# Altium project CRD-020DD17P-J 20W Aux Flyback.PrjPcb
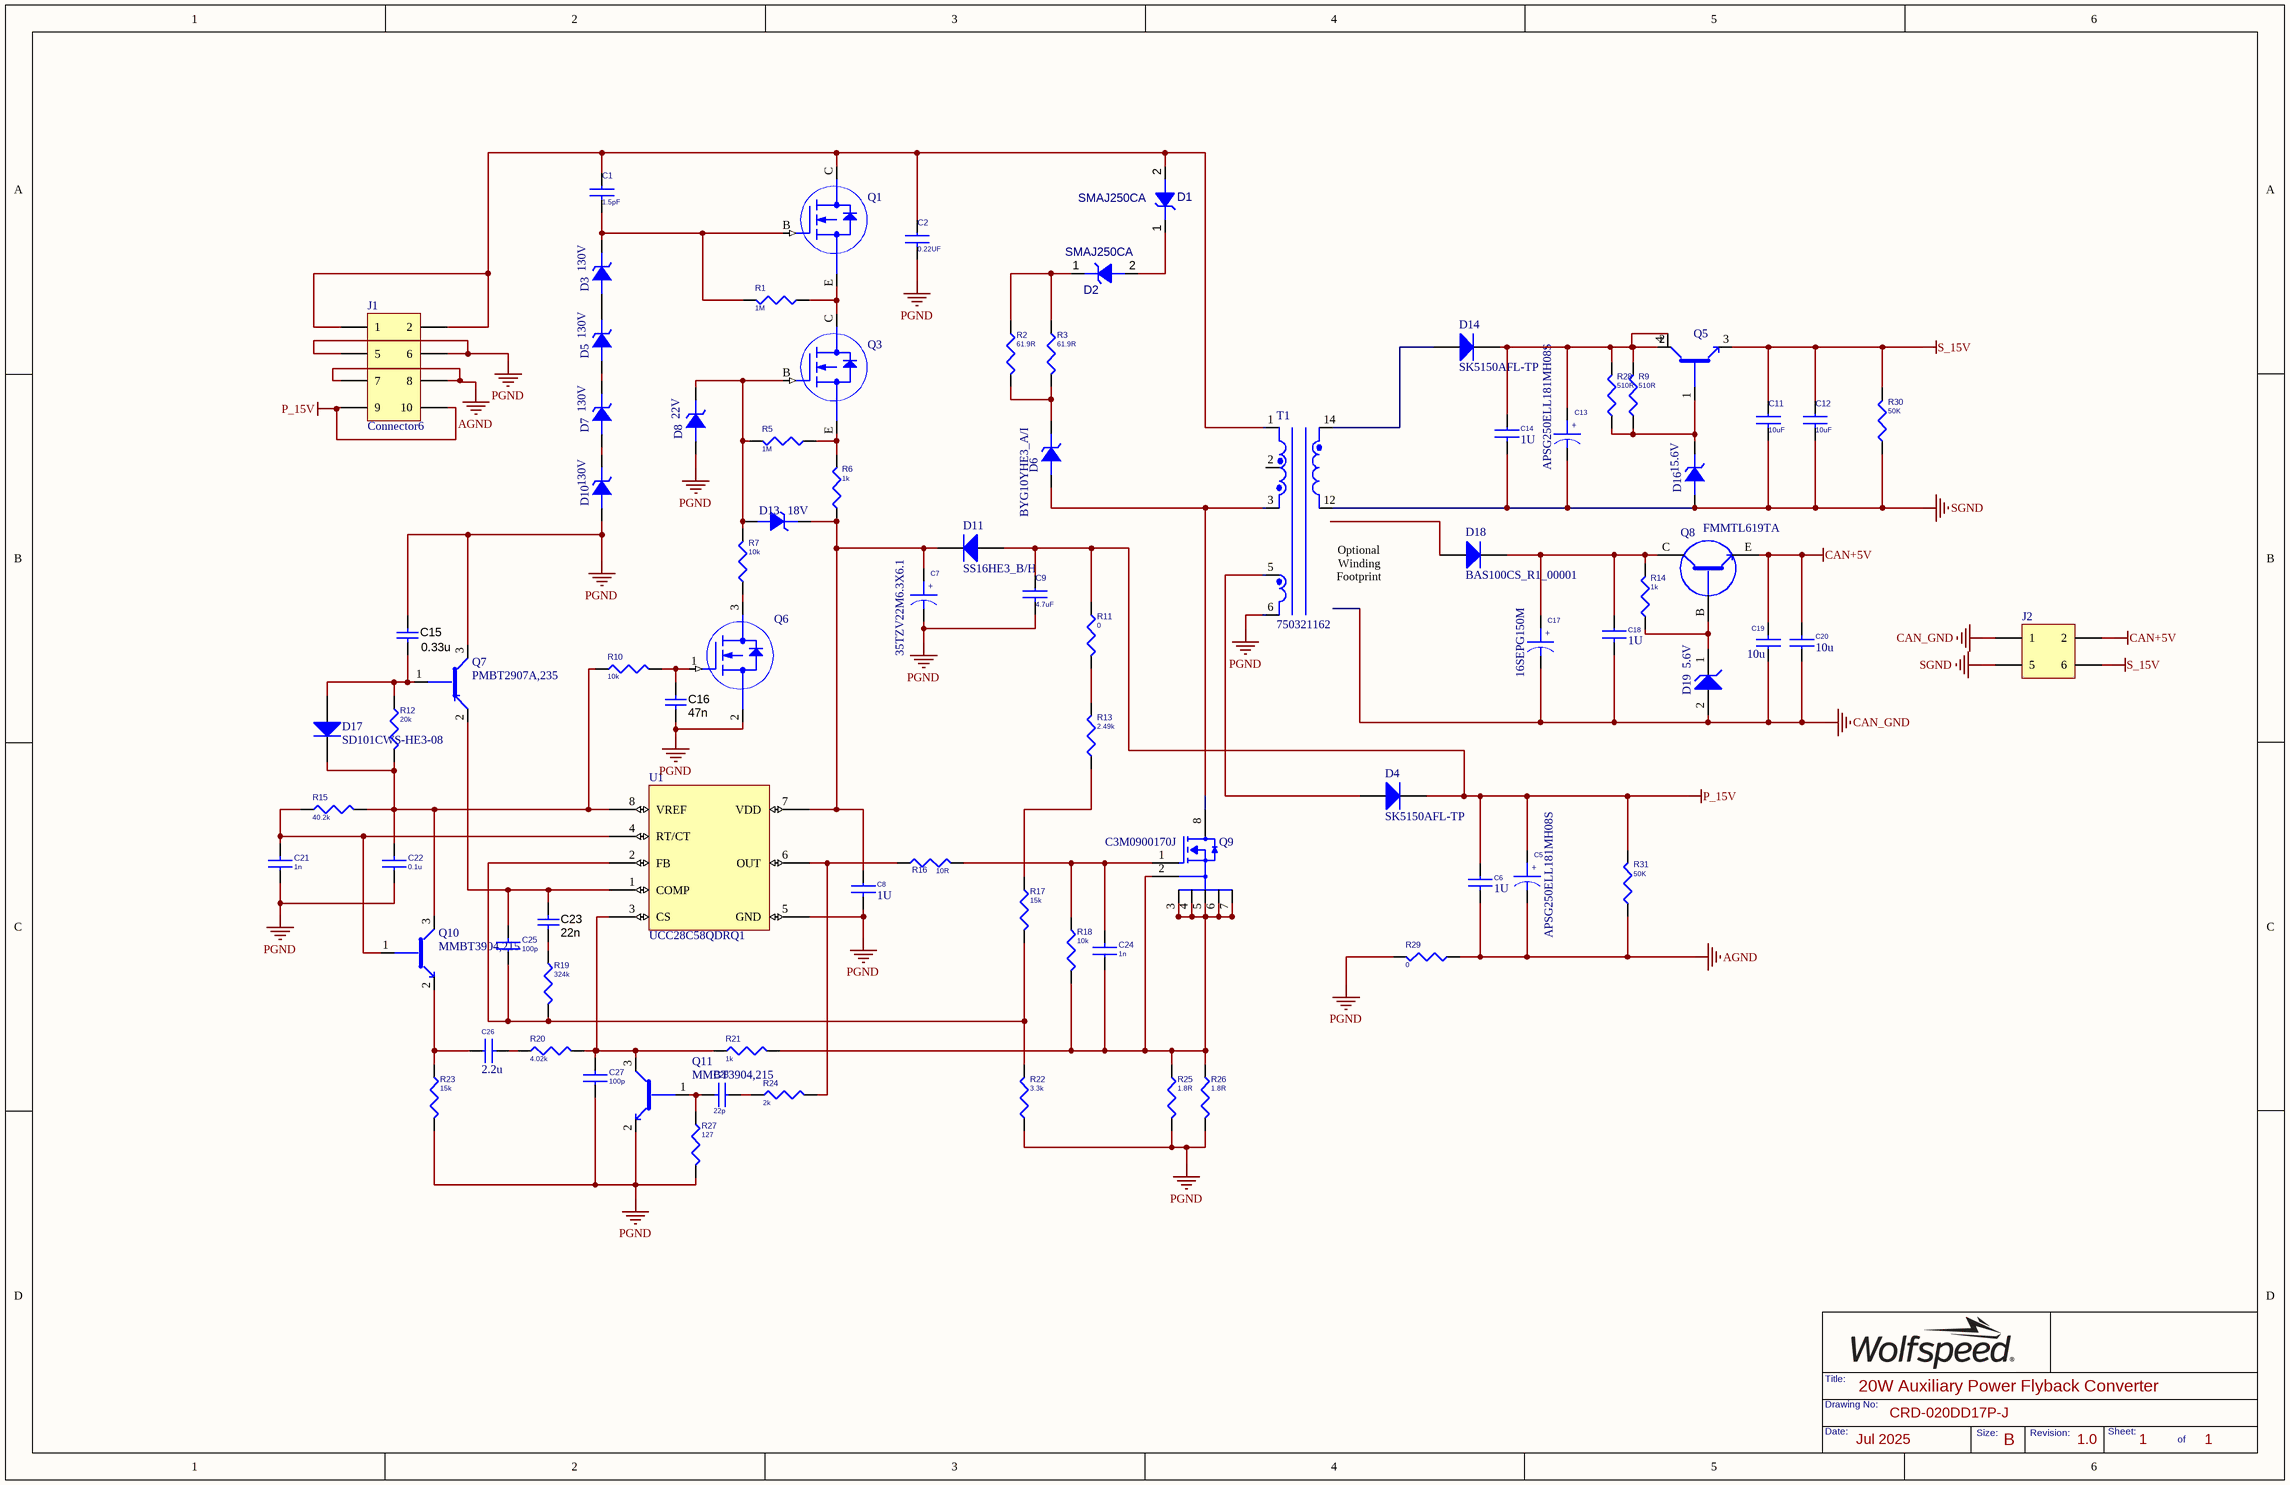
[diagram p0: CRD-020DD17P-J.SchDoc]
Title: 20W Auxiliary Power Flyback Converter; Revision: 1.0; DocumentNumber: CRD-020DD17P-J; Date: Jul 2025
1 sheet, 83 parts. Net scope: global (net labels, ports and power ports of the same name join across sheets).
Board file: CRD-020DD17P-J.PcbDoc

## Sheet CRD-020DD17P-J.SchDoc: 20W Auxiliary Power Flyback Converter
size 431 x 279 mm; SheetNumber: 1; SheetTotal: 1

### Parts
C1  1.5pF  [C1206]
C2  0.22UF  [C2220]
C5  APSG250ELL181MH08S  [C7C9C13-RNU1E221MDNASQ]
C6  1U  [C0603]
C7  35TZV22M6.3X6.1  [CAP6_6X6_6]
C8  1U  [C0603]
C9  4.7uF  [C1206]
C11  10uF  [C1206]
C12  10uF  [C1206]
C13  APSG250ELL181MH08S  [C7C9C13-RNU1E221MDNASQ]
C14  1U  [C0603]
C15  0.33u  [0603]
C16  47n  [0603]
C17  16SEPG150M  [C17_16SEPG150M]
C18  1U  [C0603]
C19  10u  [C0805]
C20  10u  [C0805]
C21  1n  [C0603]
C22  0.1u  [C0603]
C23  22n  [0603]
C24  1n  [C0603]
C25  100p  [C0603]
C26  2.2u  [0603]
C27  100p  [C0603]
C28  22p  [C0603]
D1  SMAJ250CA  [DO-214AC_SMA_B]
D2  SMAJ250CA  [DO-214AC_SMA_B]
D3  130V  [SOD-323F]
D4  SK5150AFL-TP  [DO221AC]
D5  130V  [SOD-323F]
D6  BYG10YHE3_A/I  [DO214AC]
D7  130V  [SOD-323F]
D8  22V  [SOD323]
D10  130V  [SOD-323F]
D11  SS16HE3_B/H  [SMA]
D13  18V  [SOD323]
D14  SK5150AFL-TP  [DO221AC]
D16  15.6V  [DO220AA]
D17  SD101CWS-HE3-08  [SOD323]
D18  BAS100CS_R1_00001  [SOD323]
D19  5.6V  [ONSC-SOD-123-2-425-04_V]
J1  Connector6  [HPR2X4H-254MM-80]
J2  Connector6  [HPR2X3H-254MM-90]  (value not drawn)
Q1  TO247-3  [SOT23-3]  (value not drawn)
Q3  TO247-3  [SOT23-3]  (value not drawn)
Q5  PBSS306NZ,135  [SOT223]  (value not drawn)
Q6  (no value)  [TO236AB]
Q7  PMBT2907A,235  [TO236AB]
Q8  FMMTL619TA  [SOT23-3]
Q9  C3M0900170J  [TO-263-7XL_CRW]
Q10  MMBT3904,215  [TO-236AB]
Q11  MMBT3904,215  [TO-236AB]
R1  1M  [R0603]
R2  61.9R  [R2010]
R3  61.9R  [R2010]
R5  1M  [R0603]
R6  1k  [R0603]
R7  10k  [R0603]
R9  510R  [R1206]
R10  10k  [R0603]
R11  0  [R0603]
R12  20k  [R0603]
R13  2.49k  [R0603]
R14  1k  [R0805]
R15  40.2k  [R0603]
R16  10R  [1206]
R17  15k  [R0603]
R18  10k  [R0603]
R19  324k  [R0603]
R20  4.02k  [R0603]
R21  1k  [R0603]
R22  3.3k  [R0603]
R23  15k  [R0603]
R24  2k  [R0603]
R25  1.8R  [R1206]
R26  1.8R  [R1206]
R27  127  [R0805]
R28  510R  [R1206]
R29  0  [R1206]
R30  50K  [R1206]
R31  50K  [R1206]
T1  750321162  [750345357-Footprint-1]
U1  UCC28C58QDRQ1  [SOIC-8]

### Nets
AGND: C5.2 C6.2 J1.7 J1.8 R29.1 R31.1
CAN+5V: C19.2 C20.2 J2.2 Q8.E
CAN_GND: C17.2 C18.2 C19.1 C20.1 D19.2(A) J2.1
P_15V: C5.1 C6.1 C9.1 D4.2(K) D11.1(A) J1.9 J1.10 R11.1 R31.2
PGND: C2.2 C7.2 C8.2 C9.2 C15.2 C16.1 C21.1 C22.1 C27.1 D8.1(ANODE) D10.1(ANODE) J1.5 J1.6 Q6.2(SOURCE1) Q7.3 Q11.2 R22.1 R23.2 R25.2 R26.2 R27.2 R29.2 T1.6(Pri2-) U1.5(GND)
S_15V: C11.1 C12.1 J2.6 Q5.3 R30.2
SGND: C11.2 C12.2 C13.2 C14.2 D16.1(ANODE) J2.5 R30.1 T1.12(Sec1-)
NetC1_1: C1.1 C2.1 D1.2(A) J1.1 J1.2 Q1.C T1.1(Pri1+)
NetC1_2: C1.2 D3.2(CATHODE) Q1.B R1.2
NetC7_1: C7.1 C8.1 D11.2(K) D13.2(CATHODE) R6.1 U1.7(VDD)
NetC13_1: C13.1 C14.1 D14.2(K) Q5.2 Q5.4 R9.2 R28.2
NetC15_1: C15.1 D17.1(A) Q7.1 R12.1
NetC16_2: C16.2 Q6.1(GATE) R10.2
NetC17_1: C17.1 C18.1 D18.2(K) Q8.C R14.2
NetC21_2: C21.2 Q10.1 R15.1 U1.4(RT/CT)
NetC22_2: C22.2 D17.2(K) Q10.3 R10.1 R12.2 R15.2 U1.8(VREF)
NetC23_1: C23.1 R19.1
NetC23_2: C23.2 C25.2 Q7.2 U1.1(COMP)
NetC24_1: C24.1 Q9.2(Driver_Source) Q9.3(Power_Source) Q9.4(Power_Source) Q9.5(Power_Source) Q9.6(Power_Source) Q9.7(Power_Source) R18.2 R21.2 R25.1 R26.1
NetC24_2: C24.2 Q9.1(Gate) R16.2 R18.1
NetC25_1: C25.1 R17.2 R19.2 R22.2 U1.2(FB)
NetC26_1: C26.1 Q10.2 R23.1
NetC26_2: C26.2 R20.1
NetC27_2: C27.2 Q11.3 R20.2 R21.1 U1.3(CS)
NetC28_1: C28.1 R24.1
NetC28_2: C28.2 Q11.1 R27.1
NetD1_1: D1.1(A) D2.2(A)
NetD2_1: D2.1(A) R2.1 R3.1
NetD3_1: D3.1(ANODE) D5.2(CATHODE)
NetD4_1: D4.1(A) T1.5(Pri2+)
NetD5_1: D5.1(ANODE) D7.2(CATHODE)
NetD6_1: D6.1(ANODE) Q9.8(Drain) T1.3(Pri1-)
NetD6_2: D6.2(CATHODE) R2.2 R3.2
NetD7_1: D7.1(ANODE) D10.2(CATHODE)
NetD8_2: D8.2(CATHODE) D13.1(ANODE) Q3.B R5.2 R7.2
NetD14_1: D14.1(A) T1.14(Sec1+)
NetD16_2: D16.2(CATHODE) Q5.1 R9.1 R28.1
NetD19_1: D19.1(K) Q8.B R14.1
NetQ1_E: Q1.E Q3.C R1.1
NetQ3_E: Q3.E R5.1 R6.2
NetQ6_3: Q6.3(DRAIN) R7.1
NetR11_2: R11.2 R13.2
NetR13_1: R13.1 R17.1
NetR16_1: R16.1 R24.2 U1.6(OUT)

Not connected (* = marked no-connect by the designer): D18 1(A); T1 2(Pri1+)

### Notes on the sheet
- (near T1) Optional Winding Footprint

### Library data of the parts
C1 = CAP NP_Dup1: CAP CER 1.5PF 1KV C0G/NP0 1206; Manufacturer: Knowles Syfer; PN: 1206Y1K01P50DAR
C2 = CAP NP_Dup1: CAP CER 0.22UF 1.2KV X7R 2220; Manufacturer: Knowles Syfer; PCB Footprint: C1206; PN: 2220Y1K20224KXTWS3
C5 C13 = CAP POL: CAP ALUM POLY 180UF 20% 25V T/H; Manufacturer: UCC; PCB Footprint: ecap_d18p7_5
C6 C8 C14 C18 = CAP NP: CAP CER 1UF 25V X7R 0603; Manufacturer: Murata; PN: GRM188R71E105KA12D
C7 = CAP POL: CAP ALUM 22UF 20% 35V SMD; Manufacturer: Rubycon; PCB Footprint: ecap_d18p7_5
C9 = CAP NP_Dup1: CAP CER 4.7UF 50V X7R 1206; Manufacturer: Yageo; PN: CC1206KFX7R9BB475
C11 C12 = CAP NP_Dup1: CAP CER 10UF 25V X7R 1206; Manufacturer: Yageo; PN: CC1206KKX7R8BB106
C15 = CGA3E2X7R1E104K080AA: CAP CER 0.33UF 25V X7R 0603; Manufacturer: Yageo; Polarized: N; CompType: Capacitor; Value: 0.1uF; ValueDisplayed: 33n; U/M: EA; Cap_F: 0.0000001; Tolerance_%: 10; VDC_V: 25; TaMin_C: -55; TaMax_C: 125; SizeArea_mm2: 1.28; SizeAreaWB_mm2: 4.68; SizeX_mm: 1.6; SizeY_mm: 0.8; SizeZ_mm: 1; AEC Category: Q200; AEC Qualified: Y; PN: CC0603KRX7R8BB334
C16 = CGA3E2X7R1E104K080AA: CAP CER 0.047UF 50V X7R 0603; Manufacturer: Yageo; Polarized: N; CompType: Capacitor; Value: 0.1uF; ValueDisplayed: 33n; U/M: EA; Cap_F: 0.0000001; Tolerance_%: 10; VDC_V: 25; Value2: 25V; TaMin_C: -55; TaMax_C: 125; SizeArea_mm2: 1.28; SizeAreaWB_mm2: 4.68; SizeX_mm: 1.6; SizeY_mm: 0.8; SizeZ_mm: 1; AEC Category: Q200; AEC Qualified: Y; PN: AC0603KRX7R9BB473
C17 = CAP POL: CAP ALUM POLY 150UF 20% 16V T/H; Manufacturer: Panasonic; PCB Footprint: ecap_d18p7_5
C19 C20 = CAP NP: CAP CER 10UF 16V X7R 0805; Manufacturer: Yageo; PCB Footprint: 0805; PN: CC0805MKX7R7BB106
C21 C24 = CAP NP_Dup1: CAP CER 1000PF 25V X7R 0603; Manufacturer: Yageo; PN: CC0603MRX7R9BB102
C22 = CAP NP_Dup1: CAP CER 0.1UF 50V X7R 0603; Manufacturer: Yageo; PN: CC0603MRX7R9BB104
C23 = CGA3E2X7R1E104K080AA: CAP CER 0.022UF 50V X7R 0603; Manufacturer: Yageo; Polarized: N; CompType: Capacitor; Value: 0.1uF; ValueDisplayed: 33n; U/M: EA; Cap_F: 0.0000001; Tolerance_%: 10; VDC_V: 25; Value2: 25V; TaMin_C: -55; TaMax_C: 125; SizeArea_mm2: 1.28; SizeAreaWB_mm2: 4.68; SizeX_mm: 1.6; SizeY_mm: 0.8; SizeZ_mm: 1; AEC Category: Q200; AEC Qualified: Y; PN: AC0603KRX7R9BB223
C25 C27 = CAP NP_Dup1: CAP CER 100PF 25V X7R 0603; Manufacturer: Yageo; PN: CC0603MRX7R9BB101
C26 = CAP NP: CAP CER 2.2UF 25V X7R 0603; Manufacturer: Murata; PCB Footprint: C0805; PN: GRM188Z71E225ME43D
C28 = CAP NP_Dup1: CAP CER 22PF 50V C0G/NPO 0603; Manufacturer: Yageo; PN: CC0603KRNPO9BN220
D1 D2 = CMP-004-00090-2: TVS DIODE 250VWM 405VC DO214AC405V Clamp 1A Ipp Tvs Diode Surface Mount DO-214AC; Manufacturer: Littlefuse
D3 D5 D7 D10 = DIODE ZENER1: DIODE ZENER 130V 200MW UMD2; Manufacturer: Rohm; PN: UDZLVFHTE-17130
D4 D14 = Diode: DIODE SCHOTTKY 150V 5A DO221AC; Manufacturer: MCC
D6 = DIODE ZENER1: DIODE AVAL 1.6KV 1.5A DO214AC; Manufacturer: Vishay
D8 = DIODE ZENER1: DIODE ZENER 22V 200MW SOD323; PN: BZX384C22-E3-08
D11 = Diode: DIODE SCHOTTKY 60V 1A DO214AC; Manufacturer: Vishay
D13 = DIODE ZENER1: DIODE ZENER 18V 200MW SOD323; PN: GDZ18B-HE3-18
D16 = DIODE ZENER1: DIODE ZENER 15.6V 600MW DO220AA; Manufacturer: Vishay; PN: PTV15B-M3/84A
D17 = Diode: DIODE SCHOTTKY 40V 30MA SOD323; Manufacturer: Vishay
D18 = Diode: DIODE SCHOTTKY 100V 500MA SOD323; Manufacturer: Panjit
D19 = CMP-004-00055-4: Zener Diode 5.6 V 500 mW ±5% Surface Mount SOD-123; Manufacturer: Diodes; Forward Voltage: 900mV; PN: MMSZ5232B-7-F
J1 = Connector6_1_2: CONN HEADER R/A 6POS 2.54MM; Manufacturer: Adam Tech; PN: PH2RA-06-UA
J2 = Connector6_1_1: CONN HEADER R/A 6POS 2.54MM; Manufacturer: Adam Tech; PN: PH2RA-06-UA
Q1 Q3 = TO247-3: MOSFET N-CH 600V 21MA SOT23-3; Manufacturer: Infineon; PN: BSS126H6906XTSA1
Q5 = SOT223: TRANS NPN 100V 5.1A SOT223; Manufacturer: Nexperia
Q6 = TO247-3: MOSFET N-CH 600V 21MA SOT23-3; Manufacturer: Nexperia; PN: NX7002AK,215
Q7 = SOT23-3_1: TRANS PNP 60V 0.6A TO236AB; Manufacturer: Nexperia
Q8 = SOT23-3: TRANS NPN 50V 1.25A SOT23-3; Manufacturer: DIODES
Q9 = CMP-013-00114-3: 1700V 900 M SIC MOSFET; Manufacturer: Wolfspeed; Transistor Type: N-Channel Enhancement Mode MOSFET
Q10 Q11 = SOT23-3: TRANS NPN 40V 0.2A TO236AB; Manufacturer: Nexperia
R1 R5 = R: RES 1M OHM 1% 1/10W 0603; Manufacturer: Yageo; PN: RC0603FR-071ML
R2 R3 = R: RES SMD 61.9 OHM 1% 3/4W 2010; Manufacturer: Yageo; PCB Footprint: R0603; PN: CRCW201061R9FKEF
R6 R21 = R: RES SMD 1K OHM 1% 1/10W 0603; Manufacturer: Yageo; PN: AC0603FR-071KL
R7 R10 R18 = R: RES SMD 10K OHM 1% 1/10W 0603; Manufacturer: Yageo; PN: AC0603FR-0710KL
R9 R28 = R: RES 510R OHM 5% 1/2W 1206; Manufacturer: Yageo; PN: SR1206JR-7W1KL
R11 = R: RES SMD 0 OHM 1% 1/10W 0603; Manufacturer: Yageo; PN: AC0603FR-070RL
R12 = R: RES SMD 20K OHM 1% 1/10W 0603; Manufacturer: Yageo; PN: AC0603FR-0720KL
R13 = R: RES SMD 2.49K OHM 1% 1/10W 0603; Manufacturer: Yageo; PN: RC0603FR-132K49L
R14 = R: RES SMD 1K OHM 1% 1/8W 0805; Manufacturer: Yageo; PCB Footprint: R0603; PN: RC0805FR-071KP
R15 = R: RES SMD 40.2K OHM 1% 1/10W 0603; Manufacturer: Yageo; PN: AC0603FR-0740K2L
R16 = R: RES 10 OHM 1% 1/4W 1206; Manufacturer: Yageo; PCB Footprint: R1206; PN: RC1206FR-0710RL
R17 = R: RES SMD 15K OHM 1% 1/10W 0603; Manufacturer: Yageo; PN: AT0603FRE0715KL
R19 = R: RES SMD 324K OHM 1% 1/10W 0603; Manufacturer: Yageo; PN: AC0603FR-07324KL
R20 = R: RES SMD 4.02K OHM 1% 1/10W 0603; Manufacturer: Yageo; PN: AC0603FR-074K02L
R22 = R: RES SMD 3.3K OHM 1% 1/10W 0603; Manufacturer: Yageo; PN: RE0603FRE073K3L
R23 = R: RES SMD 15K OHM 1% 1/10W 0603; Manufacturer: Yageo; PN: AC0603FR-0715KL
R24 = R: RES SMD 2K OHM 1% 1/10W 0603; Manufacturer: Yageo; PN: AC0603FR-072KL
R25 R26 = R: RES SMD 1.8 OHM 1% 3/4W 1206; Manufacturer: Vishay; PCB Footprint: R0603; PN: CRCW12061R80FKEAHP
R27 = R: RES 127 OHM 1% 1/8W 0805; Manufacturer: Yageo; PCB Footprint: R0603; PN: RC0805FR-07127RL
R29 = R: RES 0 OHM JUMPER 1/4W 1206; Manufacturer: Yageo; PCB Footprint: R0603; PN: RC1206JR-070RL
R30 R31 = R: RES 50K OHM 5% 1/2W 1206; Manufacturer: Yageo; PN: SR1206JR-7W1KL
T1 = CMP-012-00017-1: TRANSFORMERS 800uH; Manufacturer: Wurth Electronics
U1 = UCC28C56H: INDUSTRIAL, 30-V, LOW-POWER CURR; Manufacturer: TI; PN: UCC28C56HDR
